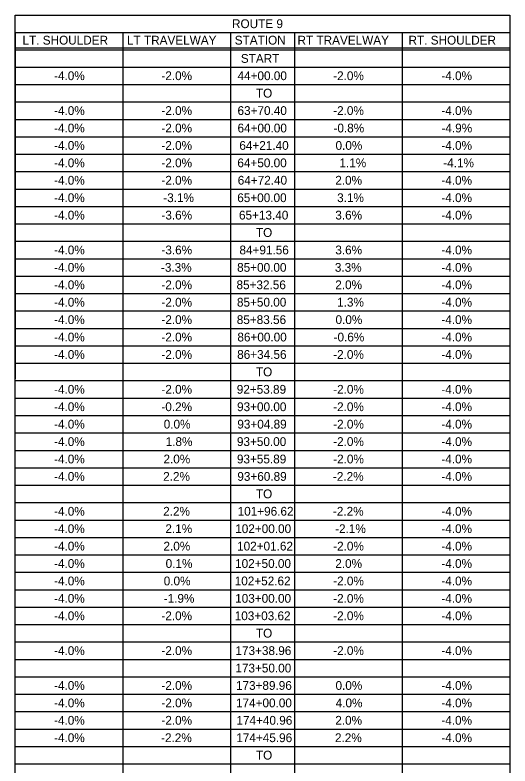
# Model space of a CAD drawing. Extents: x -15318841 to 1762012, y 465773 to 3693661.
# Drawn here: x -15317075.3 to -15316906.4, y 3692762.8 to 3693019 of the extents above; entities that cross this region are included whole.
import ezdxf

# ---------------------------------------------------------------- set-up
doc = ezdxf.new("R2010")
doc.units = 0
doc.layers.add('BORDER', color=7, linetype='Continuous')
doc.layers.add('DIMENSIONS', color=7, linetype='Continuous')

msp = doc.modelspace()

# ---------------------------------------------------------------- linework, layer by layer
at = {"layer": 'BORDER'}
for p, q in [((-15317075.32, 3693013.06), (-15317075.32, 3692894.86)), ((-15317038.55, 3693013.06), (-15317038.55, 3692507.99)), ((-15317001.78, 3693013.06), (-15317001.78, 3692507.99)), ((-15316979.91, 3693013.06), (-15316979.91, 3692507.99)), ((-15316943.14, 3693013.06), (-15316943.14, 3692507.99)), ((-15317075.32, 3693007.77), (-15316906.37, 3693007.77)), ((-15317075.32, 3693007.18), (-15316906.37, 3693007.18)), ((-15317075.32, 3693001.24), (-15316906.37, 3693001.24)), ((-15317075.32, 3693001.24), (-15316906.37, 3693001.24)), ((-15317075.32, 3693001.24), (-15316906.37, 3693001.24)), ((-15317075.32, 3692995.29), (-15316906.37, 3692995.29)), ((-15317075.32, 3692989.35), (-15316906.37, 3692989.35)), ((-15317075.32, 3692983.41), (-15316906.37, 3692983.41)), ((-15317075.32, 3692977.47), (-15316906.37, 3692977.47)), ((-15317075.32, 3692971.52), (-15316906.37, 3692971.52)), ((-15317075.32, 3692965.58), (-15316906.37, 3692965.58)), ((-15317075.32, 3692959.64), (-15316906.37, 3692959.64)), ((-15317075.32, 3692953.7), (-15316906.37, 3692953.7)), ((-15317075.32, 3692947.75), (-15316906.37, 3692947.75)), ((-15317075.32, 3692941.81), (-15316906.37, 3692941.81)), ((-15317075.32, 3692935.87), (-15316906.37, 3692935.87)), ((-15317075.32, 3692929.92), (-15316906.37, 3692929.92)), ((-15317075.32, 3692923.98), (-15316906.37, 3692923.98)), ((-15317075.32, 3692918.04), (-15316906.37, 3692918.04)), ((-15317075.32, 3692912.1), (-15316906.37, 3692912.1)), ((-15317075.32, 3692906.15), (-15316906.37, 3692906.15)), ((-15317075.32, 3692900.21), (-15316906.37, 3692900.21)), ((-15317075.32, 3692894.27), (-15316906.37, 3692894.27)), ((-15317075.32, 3692888.33), (-15316906.37, 3692888.33)), ((-15317075.32, 3692882.38), (-15316906.37, 3692882.38)), ((-15317075.32, 3692876.44), (-15316906.37, 3692876.44)), ((-15317075.32, 3692870.5), (-15316906.37, 3692870.5)), ((-15317075.32, 3692864.55), (-15316906.37, 3692864.55)), ((-15317075.32, 3692858.61), (-15316906.37, 3692858.61)), ((-15317075.32, 3692852.67), (-15316906.37, 3692852.67)), ((-15317075.32, 3692846.73), (-15316906.37, 3692846.73)), ((-15317075.32, 3692840.78), (-15316906.37, 3692840.78)), ((-15317075.32, 3692834.84), (-15316906.37, 3692834.84)), ((-15317075.32, 3692828.9), (-15316906.37, 3692828.9)), ((-15317075.32, 3692822.96), (-15316906.37, 3692822.96)), ((-15317075.32, 3692817.01), (-15316906.37, 3692817.01)), ((-15317075.32, 3692811.07), (-15316906.37, 3692811.07)), ((-15317075.32, 3692805.13), (-15316906.37, 3692805.13)), ((-15317075.32, 3692799.19), (-15316906.37, 3692799.19)), ((-15317075.32, 3692793.24), (-15316906.37, 3692793.24)), ((-15317075.32, 3692787.3), (-15316906.37, 3692787.3)), ((-15317075.32, 3692781.36), (-15316906.37, 3692781.36)), ((-15317075.32, 3692775.41), (-15316906.37, 3692775.41)), ((-15317075.32, 3692769.47), (-15316906.37, 3692769.47)), ((-15317075.32, 3692763.53), (-15316906.37, 3692763.53))]:
    msp.add_line(p, q, dxfattribs=at)
for points in [[(-15317075.32, 3693013.06), (-15317075.32, 3693019), (-15316906.37, 3693019), (-15316906.37, 3693013.06)], [(-15317075.32, 3692507.99), (-15317075.32, 3693007.15), (-15316906.37, 3693007.15), (-15316906.37, 3692507.99)]]:
    msp.add_lwpolyline(points, dxfattribs=at)
msp.add_lwpolyline([(-15317075.32, 3693013.06), (-15316906.37, 3693013.06), (-15316906.37, 3692507.99), (-15317075.32, 3692507.99)], close=True, dxfattribs=at)

# ---------------------------------------------------------------- texts
at = {"layer": 'DIMENSIONS'}
for s, p in [('ROUTE 9', (-15317001.25, 3693014.53)), ('LT. SHOULDER', (-15317072.76, 3693008.92)), ('LT TRAVELWAY', (-15317037.1, 3693008.92)), ('STATION', (-15317000.32, 3693008.92)), ('RT TRAVELWAY', (-15316978.89, 3693008.92)), ('RT. SHOULDER', (-15316941.01, 3693008.92)), ('START', (-15316998.24, 3693002.69)), ('-4.0%', (-15317061.99, 3692996.78)), ('-2.0%', (-15317025.36, 3692996.78)), ('44+00.00', (-15316999.37, 3692996.78)), ('-2.0%', (-15316966.72, 3692996.78)), ('-4.0%', (-15316929.81, 3692996.78)), ('TO', (-15316993.09, 3692990.84)), ('-4.0%', (-15317061.99, 3692984.9)), ('-2.0%', (-15317025.36, 3692984.9)), ('63+70.40', (-15316999.37, 3692984.9)), ('-2.0%', (-15316966.72, 3692984.9)), ('-4.0%', (-15316929.81, 3692984.9)), ('-4.0%', (-15317061.99, 3692978.95)), ('-2.0%', (-15317025.36, 3692978.95)), ('64+00.00', (-15316999.37, 3692978.95)), ('-0.8%', (-15316966.62, 3692978.95)), ('-4.9%', (-15316929.76, 3692978.95)), ('-4.0%', (-15317061.99, 3692973.01)), ('-2.0%', (-15317025.36, 3692973.01)), ('64+21.40', (-15316998.75, 3692973.01)), ('0.0%', (-15316965.92, 3692973.01)), ('-4.0%', (-15316929.81, 3692973.01)), ('-4.0%', (-15317061.99, 3692967.07)), ('-2.0%', (-15317025.36, 3692967.07)), ('64+50.00', (-15316999.42, 3692967.07)), ('1.1%', (-15316964.59, 3692967.07)), ('-4.1%', (-15316929.15, 3692967.07)), ('-4.0%', (-15317061.99, 3692961.13)), ('-2.0%', (-15317025.36, 3692961.13)), ('64+72.40', (-15316999.3, 3692961.13)), ('2.0%', (-15316966.01, 3692961.13)), ('-4.0%', (-15316929.81, 3692961.13)), ('-4.0%', (-15317061.99, 3692955.18)), ('-3.1%', (-15317024.72, 3692955.18)), ('65+00.00', (-15316999.46, 3692955.18)), ('3.1%', (-15316965.37, 3692955.18)), ('-4.0%', (-15316929.81, 3692955.18)), ('-4.0%', (-15317061.99, 3692949.24)), ('-3.6%', (-15317025.34, 3692949.24)), ('65+13.40', (-15316998.87, 3692949.24)), ('3.6%', (-15316965.99, 3692949.24)), ('-4.0%', (-15316929.81, 3692949.24)), ('TO', (-15316993.09, 3692943.3)), ('-4.0%', (-15317061.99, 3692937.35)), ('-3.6%', (-15317025.34, 3692937.35)), ('84+91.56', (-15316998.71, 3692937.35)), ('3.6%', (-15316965.99, 3692937.35)), ('-4.0%', (-15316929.81, 3692937.35)), ('-4.0%', (-15317061.99, 3692931.41)), ('-3.3%', (-15317025.5, 3692931.41)), ('85+00.00', (-15316999.51, 3692931.41)), ('3.3%', (-15316966.15, 3692931.41)), ('-4.0%', (-15316929.81, 3692931.41)), ('-4.0%', (-15317061.99, 3692925.47)), ('-2.0%', (-15317025.36, 3692925.47)), ('85+32.56', (-15316999.72, 3692925.47)), ('2.0%', (-15316966.01, 3692925.47)), ('-4.0%', (-15316929.81, 3692925.47)), ('-4.0%', (-15317061.99, 3692919.53)), ('-2.0%', (-15317025.36, 3692919.53)), ('85+50.00', (-15316999.56, 3692919.53)), ('1.3%', (-15316965.37, 3692919.53)), ('-4.0%', (-15316929.81, 3692919.53)), ('-4.0%', (-15317061.99, 3692913.58)), ('-2.0%', (-15317025.36, 3692913.58)), ('85+83.56', (-15316999.63, 3692913.58)), ('0.0%', (-15316965.92, 3692913.58)), ('-4.0%', (-15316929.81, 3692913.58)), ('-4.0%', (-15317061.99, 3692907.64)), ('-2.0%', (-15317025.36, 3692907.64)), ('86+00.00', (-15316999.42, 3692907.64)), ('-0.6%', (-15316966.58, 3692907.64)), ('-4.0%', (-15316929.81, 3692907.64)), ('-4.0%', (-15317061.99, 3692901.7)), ('-2.0%', (-15317025.36, 3692901.7)), ('86+34.56', (-15316999.49, 3692901.7)), ('-2.0%', (-15316966.72, 3692901.7)), ('-4.0%', (-15316929.81, 3692901.7)), ('TO', (-15316993.09, 3692895.76)), ('-4.0%', (-15317061.99, 3692889.81)), ('-2.0%', (-15317025.36, 3692889.81)), ('92+53.89', (-15316999.63, 3692889.81)), ('-2.0%', (-15316966.72, 3692889.81)), ('-4.0%', (-15316929.81, 3692889.81)), ('-4.0%', (-15317061.99, 3692883.87)), ('-0.2%', (-15317025.36, 3692883.87)), ('93+00.00', (-15316999.53, 3692883.87)), ('-2.0%', (-15316966.72, 3692883.87)), ('-4.0%', (-15316929.81, 3692883.87)), ('-4.0%', (-15317061.99, 3692877.93)), ('0.0%', (-15317024.56, 3692877.93)), ('93+04.89', (-15316999.44, 3692877.93)), ('-2.0%', (-15316966.72, 3692877.93)), ('-4.0%', (-15316929.81, 3692877.93)), ('-4.0%', (-15317061.99, 3692871.98)), ('1.8%', (-15317023.9, 3692871.98)), ('93+50.00', (-15316999.58, 3692871.98)), ('-2.0%', (-15316966.72, 3692871.98)), ('-4.0%', (-15316929.81, 3692871.98)), ('-4.0%', (-15317061.99, 3692866.04)), ('2.0%', (-15317024.65, 3692866.04)), ('93+55.89', (-15316999.58, 3692866.04)), ('-2.0%', (-15316966.72, 3692866.04)), ('-4.0%', (-15316929.81, 3692866.04)), ('-4.0%', (-15317061.99, 3692860.1)), ('2.2%', (-15317024.75, 3692860.1)), ('93+60.89', (-15316999.44, 3692860.1)), ('-2.2%', (-15316966.81, 3692860.1)), ('-4.0%', (-15316929.81, 3692860.1)), ('TO', (-15316993.09, 3692854.16)), ('-4.0%', (-15317061.99, 3692848.21)), ('2.2%', (-15317024.75, 3692848.21)), ('101+96.62', (-15316999.33, 3692848.21)), ('-2.2%', (-15316966.81, 3692848.21)), ('-4.0%', (-15316929.81, 3692848.21)), ('-4.0%', (-15317061.99, 3692842.27)), ('2.1%', (-15317023.99, 3692842.27)), ('102+00.00', (-15317000.15, 3692842.27)), ('-2.1%', (-15316966.06, 3692842.27)), ('-4.0%', (-15316929.81, 3692842.27)), ('-4.0%', (-15317061.99, 3692836.33)), ('2.0%', (-15317024.65, 3692836.33)), ('102+01.62', (-15316999.52, 3692836.33)), ('-2.0%', (-15316966.72, 3692836.33)), ('-4.0%', (-15316929.81, 3692836.33)), ('-4.0%', (-15317061.99, 3692830.39)), ('0.1%', (-15317023.9, 3692830.39)), ('102+50.00', (-15317000.2, 3692830.39)), ('2.0%', (-15316966.01, 3692830.39)), ('-4.0%', (-15316929.81, 3692830.39)), ('-4.0%', (-15317061.99, 3692824.44)), ('0.0%', (-15317024.56, 3692824.44)), ('102+52.62', (-15317000.33, 3692824.44)), ('-2.0%', (-15316966.72, 3692824.44)), ('-4.0%', (-15316929.81, 3692824.44)), ('-4.0%', (-15317061.99, 3692818.5)), ('-1.9%', (-15317024.56, 3692818.5)), ('103+00.00', (-15317000.17, 3692818.5)), ('-2.0%', (-15316966.72, 3692818.5)), ('-4.0%', (-15316929.81, 3692818.5)), ('-4.0%', (-15317061.99, 3692812.56)), ('-2.0%', (-15317025.36, 3692812.56)), ('103+03.62', (-15317000.33, 3692812.56)), ('-2.0%', (-15316966.72, 3692812.56)), ('-4.0%', (-15316929.81, 3692812.56)), ('TO', (-15316993.09, 3692806.62)), ('-4.0%', (-15317061.99, 3692800.67)), ('-2.0%', (-15317025.36, 3692800.67)), ('173+38.96', (-15317000.08, 3692800.67)), ('-2.0%', (-15316966.72, 3692800.67)), ('-4.0%', (-15316929.81, 3692800.67)), ('173+50.00', (-15317000.1, 3692794.73)), ('-4.0%', (-15317061.99, 3692788.79)), ('-2.0%', (-15317025.36, 3692788.79)), ('173+89.96', (-15316999.91, 3692788.79)), ('0.0%', (-15316965.92, 3692788.79)), ('-4.0%', (-15316929.81, 3692788.79)), ('-4.0%', (-15317061.99, 3692782.84)), ('-2.0%', (-15317025.36, 3692782.84)), ('174+00.00', (-15316999.89, 3692782.84)), ('4.0%', (-15316965.87, 3692782.84)), ('-4.0%', (-15316929.81, 3692782.84)), ('-4.0%', (-15317061.99, 3692776.9)), ('-2.0%', (-15317025.36, 3692776.9)), ('174+40.96', (-15316999.75, 3692776.9)), ('2.0%', (-15316966.01, 3692776.9)), ('-4.0%', (-15316929.81, 3692776.9)), ('-4.0%', (-15317061.99, 3692770.96)), ('-2.2%', (-15317025.46, 3692770.96)), ('174+45.96', (-15316999.79, 3692770.96)), ('2.2%', (-15316966.1, 3692770.96)), ('-4.0%', (-15316929.81, 3692770.96)), ('TO', (-15316993.09, 3692765.02))]:
    msp.add_text(s, height=3, dxfattribs=at).set_placement(p)

doc.saveas('drawing.dxf')
